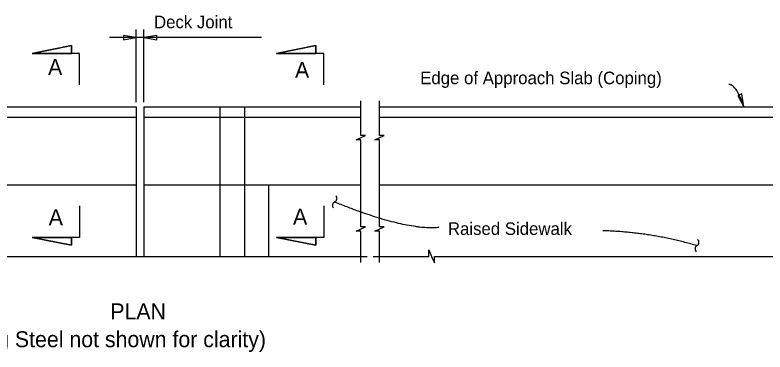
# Model space of a CAD drawing. Extents: x 0 to 40.8, y 1 to 28.
# Drawn here: x 17.72 to 29.77, y 20.27 to 25.69 of the extents above; entities that cross this region are included whole.
import ezdxf

# ---------------------------------------------------------------- set-up
doc = ezdxf.new("R2010")
doc.units = 0
for name, color, linetype in [('Dimension', 7, 'Continuous'), ('TextStructures', 7, 'Continuous'), ('TrafBarrierConc', 7, 'Continuous')]:
    doc.layers.add(name, color=color, linetype=linetype)

msp = doc.modelspace()

# ---------------------------------------------------------------- linework, layer by layer
at = {"layer": 'Dimension'}
for p, q in [((19.669, 24.288), (19.669, 25.454)), ((19.791, 24.288), (19.791, 25.454)), ((21.681, 25.326), (19.237, 25.326)), ((17.996, 25.073), (18.629, 25.2)), ((18.629, 25.2), (18.629, 25.073)), ((21.922, 25.073), (22.555, 25.2)), ((22.555, 25.2), (22.555, 25.073)), ((18.755, 25.073), (17.996, 25.073)), ((18.755, 24.567), (18.755, 25.073)), ((22.681, 25.073), (21.922, 25.073)), ((22.681, 24.567), (22.681, 25.073)), ((18.755, 22.623), (18.755, 22.116)), ((22.681, 22.623), (22.681, 22.116)), ((18.755, 22.116), (17.996, 22.116)), ((17.996, 22.116), (18.629, 21.99)), ((18.629, 21.99), (18.629, 22.116)), ((22.681, 22.116), (21.922, 22.116)), ((21.922, 22.116), (22.555, 21.99)), ((22.555, 21.99), (22.555, 22.116))]:
    msp.add_line(p, q, dxfattribs=at)
for points in [[(19.669, 25.326), (19.461, 25.361), (19.461, 25.291)], [(19.791, 25.326), (20, 25.291), (20, 25.361)], [(18.629, 25.073), (18.629, 25.2), (17.996, 25.073)], [(22.555, 25.073), (22.555, 25.2), (21.922, 25.073)], [(29.43, 24.212), (29.397, 24.421), (29.33, 24.398)], [(18.629, 22.116), (18.629, 21.99), (17.996, 22.116)], [(22.555, 22.116), (22.555, 21.99), (21.922, 22.116)]]:
    msp.add_lwpolyline(points, close=True, dxfattribs=at)
for points in [[(23.275, 22.962), (23.275, 23.686), (23.198, 23.686), (23.348, 23.752), (23.275, 23.752), (23.275, 24.312)], [(23.575, 22.962), (23.575, 23.686), (23.498, 23.686), (23.648, 23.752), (23.575, 23.752), (23.575, 24.312)], [(23.275, 21.711), (23.275, 22.219), (23.198, 22.219), (23.348, 22.286), (23.275, 22.286), (23.275, 22.962)], [(23.575, 21.711), (23.575, 22.219), (23.498, 22.219), (23.648, 22.286), (23.575, 22.286), (23.575, 22.962)], [(11.036, 21.811), (14.144, 21.811), (14.144, 21.914), (14.189, 21.811), (14.234, 21.707), (14.234, 21.811), (19.669, 21.811)], [(19.669, 21.811), (23.375, 21.811)], [(23.475, 21.811), (24.368, 21.811), (24.368, 21.914), (24.413, 21.811), (24.458, 21.707), (24.458, 21.811), (30.348, 21.811)]]:
    msp.add_lwpolyline(points, dxfattribs=at)
for centre, start, end in [((22.832, 22.741), 293.0632, 44.7905), ((22.879, 22.631), 113.0632, 224.7905), ((28.647, 22.037), 298.0989, 49.8261), ((28.703, 21.932), 118.0989, 229.8261)]:
    msp.add_arc(centre, 0.0596, start, end, dxfattribs=at)
for points in [[(29.43, 24.212), (29.307, 24.575), (29.185, 24.575)], [(22.855, 22.687), (23.993, 22.226), (24.53, 22.281)], [(28.675, 21.984), (27.92, 22.202), (27.165, 22.223)]]:
    msp.add_open_spline(points, degree=2, dxfattribs=at)
at = {"layer": 'TrafBarrierConc'}
for p, q in [((10.738, 24.212), (19.669, 24.212)), ((19.669, 24.212), (19.669, 21.811)), ((19.791, 24.212), (19.791, 21.811)), ((19.791, 24.212), (23.275, 24.212)), ((21.011, 24.212), (21.011, 21.811)), ((21.409, 24.212), (21.409, 21.811)), ((23.575, 24.212), (39.557, 24.212)), ((10.738, 24.046), (19.669, 24.046)), ((19.791, 24.046), (23.275, 24.046)), ((23.575, 24.046), (32.89, 24.046)), ((10.738, 22.962), (19.669, 22.962)), ((19.791, 22.962), (23.275, 22.962)), ((21.791, 22.962), (21.791, 21.811)), ((23.575, 22.962), (39.557, 22.962))]:
    msp.add_line(p, q, dxfattribs=at)

# ---------------------------------------------------------------- texts
at = {"layer": 'Dimension'}
for s, p in [('PLAN', (19.251, 20.8)), ('(Reinforcing Steel not shown for clarity)', (15.778, 20.352))]:
    msp.add_text(s, height=0.256, dxfattribs=at).set_placement(p)
at = {"layer": 'TextStructures'}
for s, height, p in [('Deck Joint', 0.2016, (19.953, 25.477)), ('A', 0.256, (18.251, 24.726)), ('A', 0.256, (22.218, 24.68)), ('Edge of Approach Slab (Coping)', 0.2016, (24.229, 24.578)), ('A', 0.256, (18.262, 22.312)), ('A', 0.256, (22.186, 22.322)), ('Raised Sidewalk', 0.2016, (24.674, 22.156))]:
    msp.add_text(s, height=height, dxfattribs=at).set_placement(p)

doc.saveas('drawing.dxf')
